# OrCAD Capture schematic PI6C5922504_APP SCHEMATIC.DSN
size B; title: PI6C5922504 Application Schematic; rev: 1.0; note: Diodes Inc. Clock IC Application Engineering
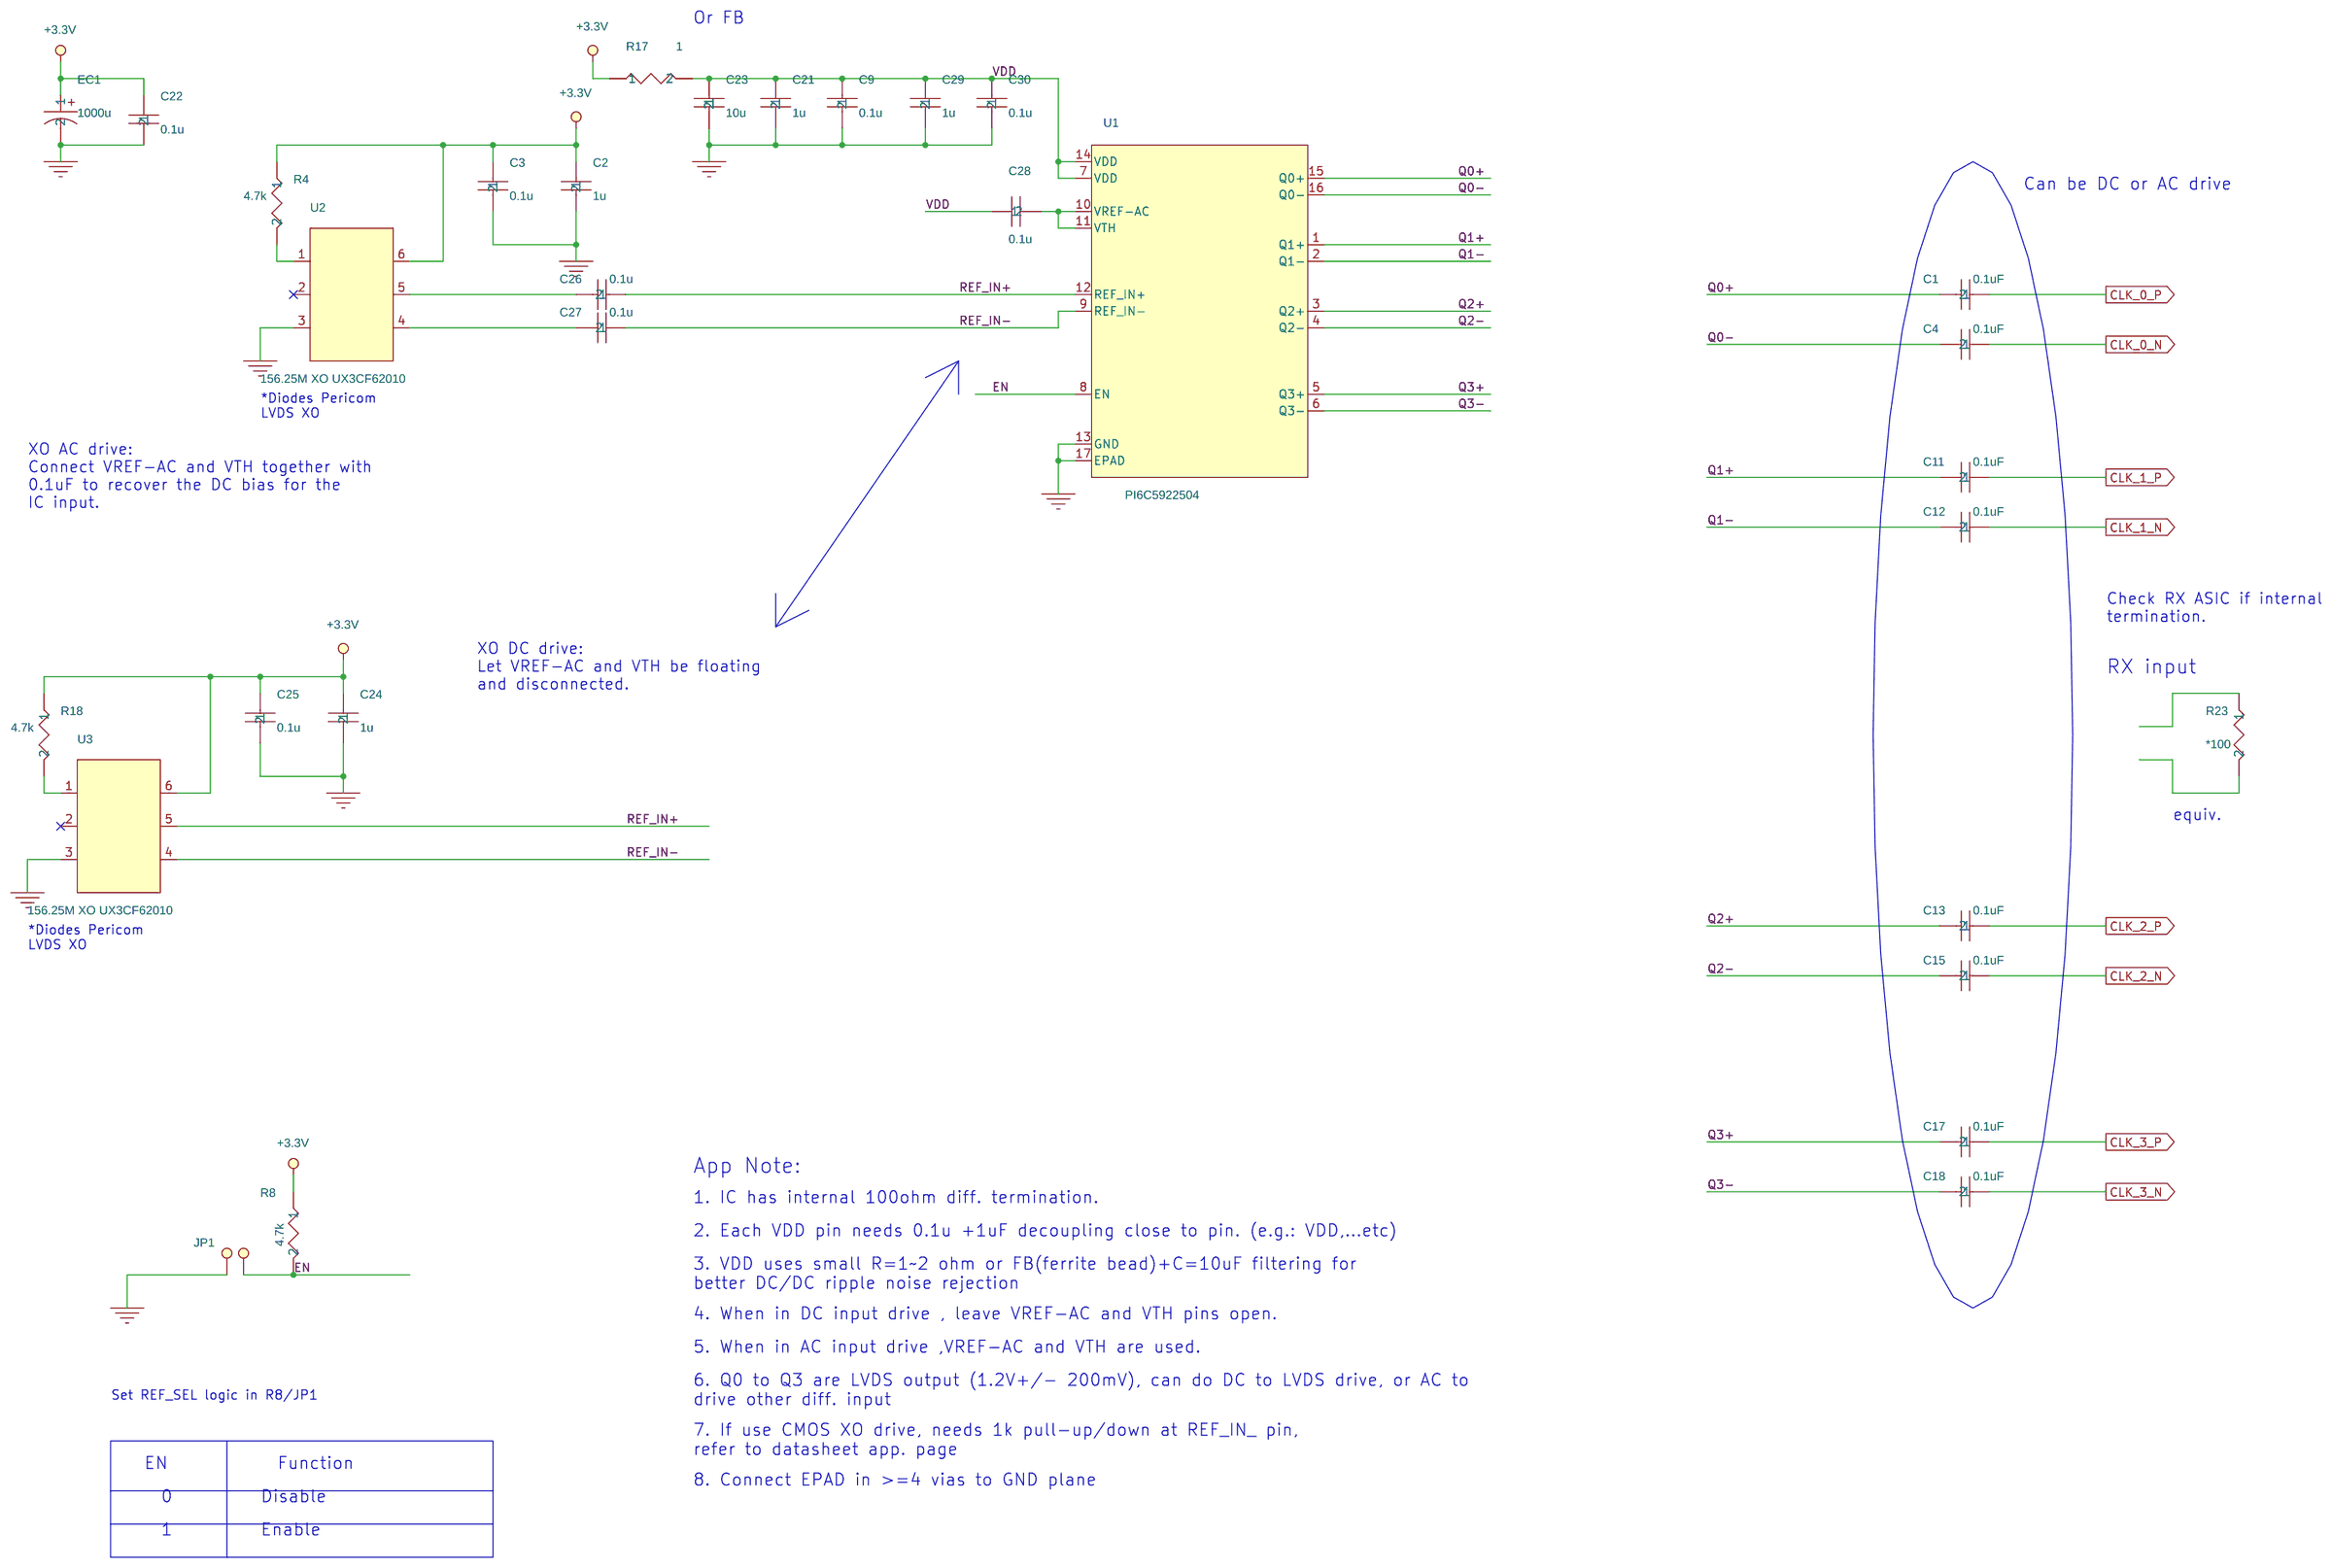
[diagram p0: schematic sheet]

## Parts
C1  0.1uF  [CC_0402]
C2  1u  [CC_0402]
C3  0.1u  [CC_0402]
C4  0.1uF  [CC_0402]
C9  0.1u  [CC_0402]
C11  0.1uF  [CC_0402]
C12  0.1uF  [CC_0402]
C13  0.1uF  [CC_0402]
C15  0.1uF  [CC_0402]
C17  0.1uF  [CC_0402]
C18  0.1uF  [CC_0402]
C21  1u  [CC_0805]
C22  0.1u  [CC_0402]
C23  10u  [CC_0805]
C24  1u  [CC_0402]
C25  0.1u  [CC_0402]
C26  0.1u  [CC_0402]
C27  0.1u  [CC_0402]
C28  0.1u  [CC_0402]
C29  1u  [CC_0805]
C30  0.1u  [CC_0402]
EC1  1000u  [CAP1000UF]
JP1  2x1 Pin Header  [2x1 Pin Header]
R4  4.7k  [R_0402]
R8  4.7k  [R_0402]
R17  1  [R_0402]
R18  4.7k  [R_0402]
R23  *100  [R_0402]
U1  PI6C5922504
U2  156.25M XO UX3CF62010  [XO 5X7]
U3  156.25M XO UX3CF62010  [XO 5X7]

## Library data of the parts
C1 = C_10n_0402_3
C2 = C_0.1u_0402_4
C3 = C_0.1u_0402_3
C4 = C_10n_0402_6
C9 = C_0.1u_0402_2
C11 = C_10n_0402_7
C12 = C_10n_0402_9
C13 = C_10n_0402_8
C15 = C_10n_0402
C17 = C_10n_0402_5
C18 = C_10n_0402_4
C21 = C_1.0u_0805_1
C22 = C_0.1u_0402_1
C23 = C_1.0u_0805
C24 = C_0.1u_0402_7
C25 = C_0.1u_0402_5
C26 = C_10n_0402_2
C27 = C_10n_0402_1
C28 = C_0.1u_0402
C29 = C_1.0u_0805_2
C30 = C_0.1u_0402_6
EC1 = C_alum_1000u
JP1 = 2x1_Pin_Header
R4 = R_0402
R8 = R_0402_1
R17 = R_0402_2
R18 = R_0402_3
R23 = R_0
U1 = PI6C4911504-03_6
U2 U3 = XO_5X7

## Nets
+3.3V: C2.1 C3.1 C22.1 C24.1 C25.1 EC1.1 R4.1 R8.1 R17.1 R18.1 U2.6 U3.6
GND: C2.2 C3.2 C9.2 C21.2 C22.2 C23.2 C24.2 C25.2 C29.2 C30.2 EC1.2 JP1.1 U1.13(GND) U1.17(EPAD) U2.3 U3.3
VDD: C9.1 C21.1 C23.1 C28.1 C29.1 C30.1 R17.2 U1.7(VDD) U1.14(VDD)
CLK_0_N: C4.1
CLK_0_P: C1.1
CLK_1_N: C12.1
CLK_1_P: C11.1
CLK_2_N: C15.1
CLK_2_P: C13.1
CLK_3_N: C18.1
CLK_3_P: C17.1
EN: JP1.2 R8.2 U1.8(EN)
Q0+: C1.2 U1.15(Q0+)
Q0-: C4.2 U1.16(Q0-)
Q1+: C11.2 U1.1(Q1+)
Q1-: C12.2 U1.2(Q1-)
Q2+: C13.2 U1.3(Q2+)
Q2-: C15.2 U1.4(Q2-)
Q3+: C17.2 U1.5(Q3+)
Q3-: C18.2 U1.6(Q3-)
REF_IN+: C26.1 U1.12(REF_IN+) U3.5
REF_IN-: C27.1 U1.9(REF_IN-) U3.4
N4608823: R4.2 U2.1
N4608911: C26.2 U2.5
N4608919: C27.2 U2.4
N4609914: R18.2 U3.1
N4640816: C28.2 U1.10(VREF-AC) U1.11(VTH)

Not connected (* = marked no-connect by the designer): R23 1 2; U2 2*; U3 2*

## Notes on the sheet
- Or FB
- Can be DC or AC drive
- *Diodes Pericom
  LVDS XO
- XO AC drive:
  Connect VREF-AC and VTH together with
  0.1uF to recover the DC bias for the
  IC input.
- Check RX ASIC if internal
  termination.
- XO DC drive:
  Let VREF-AC and VTH be floating
  and disconnected.
- RX input
- equiv.
- *Diodes Pericom
  LVDS XO
- App Note:
- 1. IC has internal 100ohm diff. termination.
- 2. Each VDD pin needs 0.1u +1uF decoupling close to pin. (e.g.: VDD,...etc)
- 3. VDD uses small R=1~2 ohm or FB(ferrite bead)+C=10uF filtering for
  better DC/DC ripple noise rejection
- 4. When in DC input drive , leave VREF-AC and VTH pins open.
- 5. When in AC input drive ,VREF-AC and VTH are used.
- Set REF_SEL logic in R8/JP1
- 6. Q0 to Q3 are LVDS output (1.2V+/- 200mV), can do DC to LVDS drive, or AC to
  drive other diff. input
- 7. If use CMOS XO drive, needs 1k pull-up/down at REF_IN_ pin,
  refer to datasheet app. page
- EN
- Function
- 0
- Disable
- 8. Connect EPAD in >=4 vias to GND plane
- 1
- Enable
